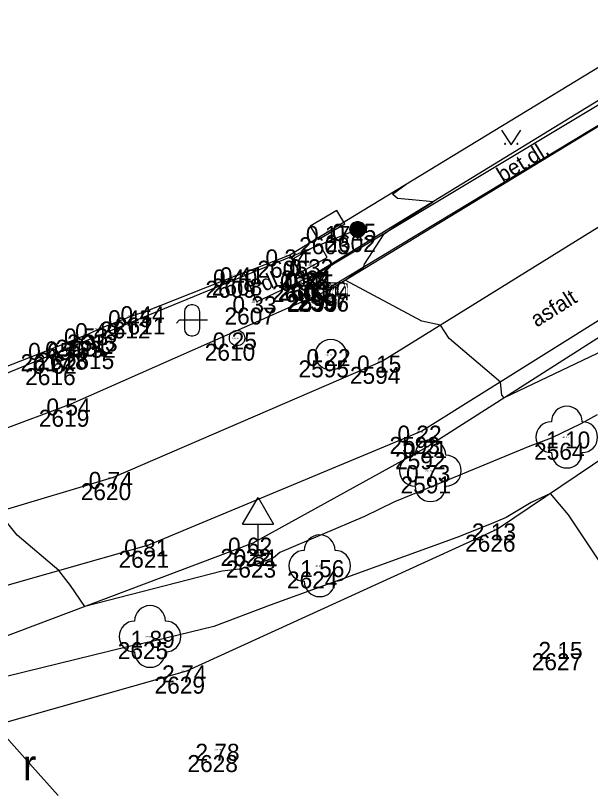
# Model space of a CAD drawing. Extents: x -740053 to -737517, y -1033516 to -1032488.
# Drawn here: x -738693.03 to -738674.39, y -1032632.11 to -1032606.84 of the extents above; entities that cross this region are included whole.
import ezdxf

# ---------------------------------------------------------------- set-up
doc = ezdxf.new("R2010")
doc.units = 0
for name, color, linetype in [('bod-cislo', 7, 'Continuous'), ('bod-oznac', 7, 'Continuous'), ('bod-vyska', 7, 'Continuous'), ('bod-vyska100', 7, 'Continuous'), ('Contours', 7, 'Continuous'), ('Contours highlighted', 7, 'Continuous'), ('dopr-zariz', 7, 'Continuous'), ('el-zariz', 7, 'Continuous'), ('nazvy-bud-povr', 7, 'Continuous'), ('objekty-na-kanalizaci', 7, 'Continuous'), ('objekty-na-vodovodu', 7, 'Continuous'), ('obrubnik', 7, 'Continuous'), ('osa-komunikace', 7, 'Continuous'), ('Ploty-Vjezd', 7, 'Continuous'), ('podezdivka', 7, 'Continuous'), ('Rozhrani-ploch', 7, 'Continuous'), ('Sdelovaci', 7, 'Continuous'), ('silnice', 7, 'Continuous'), ('Terenni-hrana', 7, 'Continuous'), ('Znacky-kultury', 7, 'Continuous')]:
    doc.layers.add(name, color=color, linetype=linetype)

# ---------------------------------------------------------------- blocks, each defined once
blk = doc.blocks.new('POINT_DISPLAY')
blk.add_line((0, 0), (0, 0))
blk = doc.blocks.new('p_strom')
for centre, start, end in [((0, 1), 0, 180), ((-1, 0), 90, 270), ((1, 0), 270, 90), ((0, -1), 180, 0)]:
    blk.add_arc(centre, 1, start, end)
at = {"rotation": -180}
blk.add_blockref('POINT_DISPLAY', (0, 0), dxfattribs=at)
blk = doc.blocks.new('po_kansa')
blk.add_circle((0, 0), 1)
blk = doc.blocks.new('_U')
for points in [[(-4999.05, -6988.837), (-4999.045, -6988.908), (-4999.045, -6988.765), (-4999.045, -6988.765)], [(-4999.045, -6988.765), (-4999.03, -6988.977), (-4999.03, -6988.696), (-4999.03, -6988.696)], [(-4999.03, -6988.977), (-4999.045, -6988.765), (-4999.045, -6988.908), (-4999.045, -6988.908)], [(-4999.03, -6988.696), (-4999.005, -6989.044), (-4999.005, -6988.629), (-4999.005, -6988.629)], [(-4999.005, -6989.044), (-4999.03, -6988.696), (-4999.03, -6988.977), (-4999.03, -6988.977)], [(-4999.005, -6988.629), (-4998.971, -6989.107), (-4998.971, -6988.566), (-4998.971, -6988.566)], [(-4998.971, -6989.107), (-4999.005, -6988.629), (-4999.005, -6989.044), (-4999.005, -6989.044)], [(-4998.971, -6988.566), (-4998.928, -6989.164), (-4998.928, -6988.509), (-4998.928, -6988.509)], [(-4998.928, -6989.164), (-4998.971, -6988.566), (-4998.971, -6989.107), (-4998.971, -6989.107)], [(-4998.928, -6988.509), (-4998.878, -6989.214), (-4998.878, -6988.459), (-4998.878, -6988.459)], [(-4998.878, -6989.214), (-4998.928, -6988.509), (-4998.928, -6989.164), (-4998.928, -6989.164)], [(-4998.878, -6988.459), (-4998.82, -6989.257), (-4998.82, -6988.416), (-4998.82, -6988.416)], [(-4998.82, -6989.257), (-4998.878, -6988.459), (-4998.878, -6989.214), (-4998.878, -6989.214)], [(-4998.82, -6988.416), (-4998.758, -6989.291), (-4998.758, -6988.382), (-4998.758, -6988.382)], [(-4998.758, -6989.291), (-4998.82, -6988.416), (-4998.82, -6989.257), (-4998.82, -6989.257)], [(-4998.758, -6988.382), (-4998.691, -6989.316), (-4998.691, -6988.357), (-4998.691, -6988.357)], [(-4998.691, -6989.316), (-4998.758, -6988.382), (-4998.758, -6989.291), (-4998.758, -6989.291)], [(-4998.691, -6988.357), (-4998.621, -6989.331), (-4998.621, -6988.342), (-4998.621, -6988.342)], [(-4998.621, -6989.331), (-4998.691, -6988.357), (-4998.691, -6989.316), (-4998.691, -6989.316)], [(-4998.621, -6988.342), (-4998.55, -6989.336), (-4998.55, -6988.337), (-4998.55, -6988.337)], [(-4998.55, -6989.336), (-4998.621, -6988.342), (-4998.621, -6989.331), (-4998.621, -6989.331)], [(-4998.55, -6988.337), (-4998.479, -6989.331), (-4998.479, -6988.342), (-4998.479, -6988.342)], [(-4998.479, -6989.331), (-4998.55, -6988.337), (-4998.55, -6989.336), (-4998.55, -6989.336)], [(-4998.479, -6988.342), (-4998.409, -6989.316), (-4998.409, -6988.357), (-4998.409, -6988.357)], [(-4998.409, -6989.316), (-4998.479, -6988.342), (-4998.479, -6989.331), (-4998.479, -6989.331)], [(-4998.409, -6988.357), (-4998.343, -6989.291), (-4998.343, -6988.382), (-4998.343, -6988.382)], [(-4998.343, -6989.291), (-4998.409, -6988.357), (-4998.409, -6989.316), (-4998.409, -6989.316)], [(-4998.343, -6988.382), (-4998.28, -6989.257), (-4998.28, -6988.416), (-4998.28, -6988.416)], [(-4998.28, -6989.257), (-4998.343, -6988.382), (-4998.343, -6989.291), (-4998.343, -6989.291)], [(-4998.28, -6988.416), (-4998.223, -6989.214), (-4998.223, -6988.459), (-4998.223, -6988.459)], [(-4998.223, -6989.214), (-4998.28, -6988.416), (-4998.28, -6989.257), (-4998.28, -6989.257)], [(-4998.223, -6988.459), (-4998.173, -6989.164), (-4998.173, -6988.509), (-4998.173, -6988.509)], [(-4998.173, -6989.164), (-4998.223, -6988.459), (-4998.223, -6989.214), (-4998.223, -6989.214)], [(-4998.173, -6988.509), (-4998.13, -6989.107), (-4998.13, -6988.566), (-4998.13, -6988.566)], [(-4998.13, -6989.107), (-4998.173, -6988.509), (-4998.173, -6989.164), (-4998.173, -6989.164)], [(-4998.13, -6988.566), (-4998.096, -6989.044), (-4998.096, -6988.629), (-4998.096, -6988.629)], [(-4998.096, -6989.044), (-4998.13, -6988.566), (-4998.13, -6989.107), (-4998.13, -6989.107)], [(-4998.096, -6988.629), (-4998.071, -6988.977), (-4998.071, -6988.696), (-4998.071, -6988.696)], [(-4998.071, -6988.977), (-4998.096, -6988.629), (-4998.096, -6989.044), (-4998.096, -6989.044)], [(-4998.071, -6988.696), (-4998.056, -6988.908), (-4998.056, -6988.765), (-4998.056, -6988.765)], [(-4998.056, -6988.908), (-4998.071, -6988.696), (-4998.071, -6988.977), (-4998.071, -6988.977)], [(-4998.05, -6988.837), (-4998.056, -6988.765), (-4998.056, -6988.908), (-4998.056, -6988.908)]]:
    blk.add_lwpolyline(points, close=True)
blk = doc.blocks.new('el_sloup')
blk.add_circle((0, 0), 0.5)
blk.add_blockref('_U', (4998.55, 6988.837))
blk = doc.blocks.new('el_rozd')
for p, q in [((-1.001, 1.001), (-1.001, 0)), ((1.001, 1.001), (-1.001, 1.001)), ((1.001, 0), (1.001, 1.001)), ((-1.001, 0), (1.001, 0))]:
    blk.add_line(p, q)
blk = doc.blocks.new('vo_soupe')
blk.add_circle((0, 0), 0.5)
blk = doc.blocks.new('d_znacka')
for p, q in [((-1, 2), (0, 3.732)), ((0, 3.732), (1, 2)), ((-1, 2), (1, 2)), ((0, 0), (0, 2)), ((-0.5, 0), (0.5, 0))]:
    blk.add_line(p, q)
blk = doc.blocks.new('p_park')
for p, q in [((-1.002, 1.5), (0, 0)), ((0, 0), (1.002, 1.5))]:
    blk.add_line(p, q)
for centre, start, end in [((-0.623, 0.102), 360, 180), ((-0.623, 0.102), 180, 360), ((0.658, 0.102), 0, 180), ((0.658, 0.102), 180, 0)]:
    blk.add_arc(centre, 0.05, start, end)
blk = doc.blocks.new('p_neplod')
for p, q in [((-0.494, 0.555), (-0.494, -0.548)), ((0.052, 1.005), (-0.044, 1.005)), ((0.502, -0.548), (0.502, 0.555)), ((-0.824, 0.004), (-0.994, -0.184)), ((1.002, 0.004), (-0.824, 0.004)), ((-0.044, -0.998), (0.052, -0.998))]:
    blk.add_line(p, q)
for centre, start, end in [((-0.044, 0.555), 90, 180), ((0.052, 0.555), 0, 90), ((-0.044, -0.548), 180, 270), ((0.052, -0.548), 270, 0)]:
    blk.add_arc(centre, 0.45, start, end)
blk = doc.blocks.new('p_orna')
blk.add_text('r', height=1.996).set_placement((-0.002, 0))

msp = doc.modelspace()

# ---------------------------------------------------------------- linework, layer by layer
at = {"layer": 'Contours'}
for points in [[(-738674.176, -1032619.78), (-738674.7, -1032620.069), (-738675.668, -1032620.535), (-738676.355, -1032620.795), (-738679.161, -1032621.954), (-738680.748, -1032622.592), (-738681.722, -1032623.069), (-738684.463, -1032624.235), (-738684.663, -1032624.409), (-738685.398, -1032624.69), (-738685.786, -1032624.784), (-738686.336, -1032624.844), (-738690.782, -1032625.989), (-738691.248, -1032625.307), (-738691.624, -1032624.827), (-738692.982, -1032623.673), (-738693.598, -1032622.921), (-738695.368, -1032622.283), (-738696.983, -1032621.582), (-738695.728, -1032620.214), (-738695.568, -1032619.535), (-738695.572, -1032619.332), (-738695.495, -1032619.066)], [(-738673.049, -1032626.1), (-738675.104, -1032623.02), (-738675.691, -1032622.326), (-738676.313, -1032622.616), (-738677.126, -1032623.104), (-738677.611, -1032623.305), (-738678.724, -1032623.751), (-738684.781, -1032625.942), (-738686.6, -1032626.638), (-738688.517, -1032627.105), (-738689.404, -1032627.297), (-738697.254, -1032629.216), (-738699.629, -1032629.462), (-738706.445, -1032630.229), (-738706.608, -1032630.027), (-738706.158, -1032628.364), (-738706.481, -1032626.699), (-738706.759, -1032626.307), (-738707.157, -1032626.093), (-738709.238, -1032624.356), (-738709.051, -1032623.478), (-738709.105, -1032623.213), (-738709.776, -1032623.115), (-738711.586, -1032622.343)], [(-738691.646, -1032632.111), (-738692.477, -1032631.182), (-738693.678, -1032629.842), (-738696.076, -1032630.361), (-738697.04, -1032630.597), (-738703.814, -1032631.3), (-738707.302, -1032631.693), (-738712.466, -1032631.794), (-738712.64, -1032631.79)]]:
    msp.add_lwpolyline(points, dxfattribs=at)
at = {"layer": 'Contours highlighted'}
msp.add_lwpolyline([(-738670.249, -1032615.922), (-738677.188, -1032619.224), (-738677.266, -1032619.14), (-738677.314, -1032618.716), (-738678.978, -1032617.306), (-738679.251, -1032616.874), (-738679.855, -1032616.74), (-738682.347, -1032615.419), (-738682.342, -1032615.414), (-738681.753, -1032614.998), (-738681.721, -1032614.9), (-738681.079, -1032613.907), (-738680.604, -1032613.578), (-738679.494, -1032612.874), (-738680.175, -1032612.812), (-738680.65, -1032612.768), (-738680.811, -1032612.626), (-738680.367, -1032612.306)], dxfattribs=at)
at = {"layer": 'obrubnik'}
for p, q in [((-738673.35, -1032609.11), (-738683.52, -1032615.34)), ((-738672.98, -1032609.7), (-738682.85, -1032615.66)), ((-738683.652, -1032615.372), (-738684.14, -1032614.6)), ((-738683.67, -1032615.39), (-738683.652, -1032615.372)), ((-738683.52, -1032615.34), (-738683.652, -1032615.372)), ((-738683.19, -1032615.67), (-738683.48, -1032615.35)), ((-738683.023, -1032615.692), (-738683.19, -1032615.67)), ((-738682.85, -1032615.66), (-738683.023, -1032615.692))]:
    msp.add_line(p, q, dxfattribs=at)
at = {"layer": 'osa-komunikace'}
for p, q in [((-738671.61, -1032612.13), (-738681.13, -1032618.04)), ((-738681.13, -1032618.04), (-738689.87, -1032621.81)), ((-738689.87, -1032621.81), (-738698.33, -1032624.33))]:
    msp.add_line(p, q, dxfattribs=at)
at = {"layer": 'Ploty-Vjezd'}
for p, q in [((-738685.84, -1032615.25), (-738688.84, -1032616.44)), ((-738689.24, -1032616.57), (-738690.31, -1032616.99)), ((-738690.673, -1032617.162), (-738691.817, -1032617.629))]:
    msp.add_line(p, q, dxfattribs=at)
at = {"layer": 'podezdivka'}
for p, q in [((-738671.38, -1032606.84), (-738684.14, -1032614.6)), ((-738684.14, -1032614.6), (-738685.62, -1032615.18)), ((-738685.62, -1032615.18), (-738685.84, -1032615.25)), ((-738688.84, -1032616.44), (-738689.24, -1032616.57)), ((-738690.31, -1032616.99), (-738690.67, -1032617.16)), ((-738691.82, -1032617.63), (-738698.96, -1032620.42))]:
    msp.add_line(p, q, dxfattribs=at)
at = {"layer": 'Rozhrani-ploch'}
for p, q in [((-738673.25, -1032609.2), (-738683.48, -1032615.35)), ((-738683.67, -1032615.39), (-738684.14, -1032614.6)), ((-738685.21, -1032616.12), (-738685.62, -1032615.18)), ((-738683.67, -1032615.39), (-738685.21, -1032616.12)), ((-738683.48, -1032615.35), (-738683.67, -1032615.39)), ((-738683.19, -1032615.71), (-738683.48, -1032615.35)), ((-738683.019, -1032615.73), (-738683.19, -1032615.71)), ((-738682.81, -1032615.7), (-738683.019, -1032615.73)), ((-738690.434, -1032617.556), (-738690.673, -1032617.162)), ((-738690.67, -1032617.16), (-738690.42, -1032617.56)), ((-738690.42, -1032617.56), (-738691.67, -1032618.08)), ((-738691.666, -1032618.073), (-738690.434, -1032617.556)), ((-738691.67, -1032618.08), (-738691.82, -1032617.63)), ((-738691.817, -1032617.629), (-738691.666, -1032618.073))]:
    msp.add_line(p, q, dxfattribs=at)
at = {"layer": 'Sdelovaci'}
msp.add_line((-738681.94, -1032613.77), (-738700.2, -1032621.25), dxfattribs=at)
at = {"layer": 'silnice'}
for p, q in [((-738672.97, -1032609.72), (-738682.81, -1032615.7)), ((-738670.37, -1032614.37), (-738679.86, -1032620.31)), ((-738682.81, -1032615.7), (-738691.24, -1032619.43)), ((-738691.24, -1032619.43), (-738698.98, -1032622.33)), ((-738679.86, -1032620.31), (-738688.72, -1032624)), ((-738688.72, -1032624), (-738697.89, -1032626.61))]:
    msp.add_line(p, q, dxfattribs=at)
at = {"layer": 'Terenni-hrana'}
for p, q in [((-738666.39, -1032612.35), (-738679.68, -1032620.81)), ((-738665.38, -1032615.4), (-738677.41, -1032623.48)), ((-738679.68, -1032620.81), (-738685.34, -1032623.94)), ((-738677.41, -1032623.48), (-738687.49, -1032628.08)), ((-738685.34, -1032623.94), (-738697.37, -1032628.47)), ((-738687.49, -1032628.08), (-738697.01, -1032630.79))]:
    msp.add_line(p, q, dxfattribs=at)

# ---------------------------------------------------------------- block references
at = {"layer": 'bod-oznac'}
for p in [(-738681.94, -1032613.77), (-738682.79, -1032613.84), (-738684.14, -1032614.6), (-738683.37, -1032614.92), (-738685.84, -1032615.25), (-738685.62, -1032615.18), (-738683.67, -1032615.39), (-738683.52, -1032615.34), (-738683.48, -1032615.35), (-738683.19, -1032615.67), (-738683.19, -1032615.71), (-738682.85, -1032615.66), (-738682.81, -1032615.7), (-738685.21, -1032616.12), (-738688.84, -1032616.44), (-738689.24, -1032616.57), (-738690.31, -1032616.99), (-738690.67, -1032617.16), (-738685.85, -1032617.29), (-738690.42, -1032617.56), (-738691.82, -1032617.63), (-738691.28, -1032617.58), (-738691.67, -1032618.08), (-738682.81, -1032617.83), (-738681.13, -1032618.04), (-738691.24, -1032619.43), (-738679.86, -1032620.31), (-738675.16, -1032620.5), (-738679.68, -1032620.81), (-738679.58, -1032621.59), (-738689.87, -1032621.81), (-738677.41, -1032623.48), (-738688.72, -1032624), (-738685.34, -1032623.94), (-738685.17, -1032624.32), (-738683.17, -1032624.67), (-738688.67, -1032626.96), (-738675.25, -1032627.32), (-738687.49, -1032628.08), (-738686.41, -1032630.62)]:
    msp.add_blockref('POINT_DISPLAY', p, dxfattribs=at)
at = {"layer": 'dopr-zariz', "xscale": 0.5, "yscale": 0.5}
msp.add_blockref('d_znacka', (-738685.17, -1032624.32), dxfattribs=at)
at = {"layer": 'el-zariz'}
for p, xscale, yscale, rotation in [((-738682.79, -1032613.84), 0.49999999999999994, 0.4999999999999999, 30.52115502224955), ((-738683.37, -1032614.92), 0.5, 0.5, 29.33989546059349)]:
    msp.add_blockref('el_rozd', p, dxfattribs=dict(at, xscale=xscale, yscale=yscale, rotation=rotation))
at = {"layer": 'el-zariz', "xscale": 0.5, "yscale": 0.5}
msp.add_blockref('el_sloup', (-738681.94, -1032613.77), dxfattribs=at)
at = {"layer": 'objekty-na-kanalizaci', "xscale": 0.5, "yscale": 0.5}
msp.add_blockref('po_kansa', (-738682.81, -1032617.83), dxfattribs=at)
at = {"layer": 'objekty-na-vodovodu', "xscale": 0.5, "yscale": 0.5}
msp.add_blockref('vo_soupe', (-738685.85, -1032617.29), dxfattribs=at)
at = {"layer": 'Znacky-kultury'}
for name, p, xscale, yscale in [('p_park', (-738676.966, -1032611.03), 0.31490742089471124, 0.31490742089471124), ('p_neplod', (-738687.311, -1032616.715), 0.5, 0.5), ('p_strom', (-738675.16, -1032620.5), 0.5, 0.5), ('p_strom', (-738679.58, -1032621.59), 0.5, 0.5), ('p_strom', (-738683.17, -1032624.67), 0.5, 0.5), ('p_strom', (-738688.67, -1032626.96), 0.5, 0.5), ('p_orna', (-738692.799, -1032631.62), 0.5, 0.5)]:
    msp.add_blockref(name, p, dxfattribs=dict(at, xscale=xscale, yscale=yscale))

# ---------------------------------------------------------------- texts
at = {"layer": 'bod-cislo'}
for s, p in [('2603', (-738683.838, -1032614.573)), ('2602', (-738682.988, -1032614.503)), ('2606', (-738685.188, -1032615.333)), ('2604', (-738684.431, -1032615.653)), ('2609', (-738686.875, -1032615.983)), ('2608', (-738686.668, -1032615.913)), ('2600', (-738684.528, -1032616.083)), ('2601', (-738684.489, -1032616.073)), ('2605', (-738684.718, -1032616.123)), ('2598', (-738684.238, -1032616.403)), ('2599', (-738684.225, -1032616.443)), ('2597', (-738683.898, -1032616.393)), ('2596', (-738683.858, -1032616.433)), ('2607', (-738686.258, -1032616.853)), ('2612', (-738690.288, -1032617.303)), ('2611', (-738689.809, -1032617.173)), ('2613', (-738691.358, -1032617.723)), ('2614', (-738691.731, -1032617.893)), ('2610', (-738686.898, -1032618.023)), ('2617', (-738692.868, -1032618.363)), ('2618', (-738692.328, -1032618.313)), ('2615', (-738691.468, -1032618.293)), ('2595', (-738683.858, -1032618.563)), ('2616', (-738692.718, -1032618.813)), ('2594', (-738682.191, -1032618.773)), ('2619', (-738692.275, -1032620.163)), ('2593', (-738680.908, -1032621.043)), ('2564', (-738676.221, -1032621.233)), ('2592', (-738680.728, -1032621.543)), ('2591', (-738680.549, -1032622.323)), ('2620', (-738690.918, -1032622.543)), ('2626', (-738678.458, -1032624.213)), ('2622', (-738686.388, -1032624.673)), ('2621', (-738689.689, -1032624.733)), ('2623', (-738686.218, -1032625.053)), ('2624', (-738684.231, -1032625.403)), ('2625', (-738689.718, -1032627.693)), ('2627', (-738676.298, -1032628.053)), ('2629', (-738688.525, -1032628.813)), ('2628', (-738687.458, -1032631.353))]:
    msp.add_text(s, height=0.55, dxfattribs=at).set_placement(p)
at = {"layer": 'bod-vyska'}
for s, p in [('0 17', (-738683.618, -1032614.207)), ('0 15', (-738682.768, -1032614.137)), ('0 34', (-738684.929, -1032614.967)), ('0 32', (-738684.159, -1032615.287)), ('0 41', (-738686.409, -1032615.547)), ('0 40', (-738686.629, -1032615.617)), ('0 37', (-738684.459, -1032615.757)), ('0 38', (-738684.309, -1032615.707)), ('0 23', (-738684.269, -1032615.717)), ('0 17', (-738684.018, -1032616.037)), ('0 11', (-738684.018, -1032616.077)), ('0 10', (-738683.678, -1032616.027)), ('0 04', (-738683.599, -1032616.067)), ('0 33', (-738685.999, -1032616.487)), ('0 44', (-738689.629, -1032616.807)), ('0 45', (-738690.029, -1032616.937)), ('0 49', (-738691.099, -1032617.357)), ('0 53', (-738691.459, -1032617.527)), ('0 25', (-738686.639, -1032617.657)), ('0 65', (-738692.622, -1032617.997)), ('0 76', (-738692.069, -1032617.947)), ('0 52', (-738691.209, -1032617.927)), ('0 22', (-738683.599, -1032618.197)), ('0 62', (-738692.472, -1032618.447)), ('0 15', (-738681.958, -1032618.407)), ('0 54', (-738692.029, -1032619.797)), ('0 22', (-738680.649, -1032620.677)), ('1 10', (-738675.831, -1032620.867)), ('0 21', (-738680.469, -1032621.177)), ('0 73', (-738680.369, -1032621.957)), ('0 74', (-738690.659, -1032622.177)), ('2 13', (-738678.238, -1032623.847)), ('0 81', (-738689.509, -1032624.367)), ('0 62', (-738686.142, -1032624.307)), ('0 81', (-738685.959, -1032624.687)), ('1 56', (-738683.802, -1032625.037)), ('1 89', (-738689.302, -1032627.327)), ('2 15', (-738676.078, -1032627.687)), ('2 74', (-738688.279, -1032628.447)), ('2 78', (-738687.199, -1032630.987))]:
    msp.add_text(s, height=0.55, dxfattribs=at).set_placement(p)
at = {"layer": 'bod-vyska100'}
for s, p in [('280 15', (-738682.111, -1032613.803)), ('280 17', (-738682.961, -1032613.873)), ('280 34', (-738684.307, -1032614.633)), ('280 32', (-738683.537, -1032614.953)), ('280 40', (-738686.007, -1032615.283)), ('280 41', (-738685.787, -1032615.213)), ('280 37', (-738683.837, -1032615.423)), ('280 38', (-738683.687, -1032615.373)), ('280 23', (-738683.647, -1032615.383)), ('280 17', (-738683.361, -1032615.703)), ('280 11', (-738683.361, -1032615.743)), ('280 10', (-738683.021, -1032615.693)), ('280 04', (-738682.977, -1032615.733)), ('280 33', (-738685.377, -1032616.153)), ('280 45', (-738689.407, -1032616.603)), ('280 44', (-738689.007, -1032616.473)), ('280 49', (-738690.477, -1032617.023)), ('280 53', (-738690.837, -1032617.193)), ('280 25', (-738686.017, -1032617.323)), ('280 76', (-738691.447, -1032617.613)), ('280 52', (-738690.587, -1032617.593)), ('280 65', (-738691.988, -1032617.663)), ('280 22', (-738682.977, -1032617.863)), ('280 62', (-738691.838, -1032618.113)), ('280 15', (-738681.301, -1032618.073)), ('280 54', (-738691.407, -1032619.463)), ('280 22', (-738680.027, -1032620.343)), ('281 10', (-738675.323, -1032620.533)), ('280 21', (-738679.847, -1032620.843)), ('280 73', (-738679.747, -1032621.623)), ('280 74', (-738690.037, -1032621.843)), ('282 13', (-738677.581, -1032623.513)), ('280 81', (-738688.887, -1032624.033)), ('280 62', (-738685.508, -1032623.973)), ('280 81', (-738685.337, -1032624.353)), ('281 56', (-738683.33, -1032624.703)), ('281 89', (-738688.83, -1032626.993)), ('282 15', (-738675.421, -1032627.353)), ('282 74', (-738687.657, -1032628.113)), ('282 78', (-738686.577, -1032630.653))]:
    msp.add_text(s, height=0.05, dxfattribs=at).set_placement(p)
at = {"layer": 'nazvy-bud-povr'}
for s, height, rotation, p in [('bet.dl.', 0.5, 31.5547, (-738677.236, -1032612.26)), ('dl.', 0.5, 24.2283, (-738684.956, -1032615.789)), ('asfalt', 0.5, 32.1173, (-738676.136, -1032616.954)), ('bet.', 0.2586, 22.1727, (-738691.368, -1032617.852))]:
    msp.add_text(s, height=height, rotation=rotation, dxfattribs=at).set_placement(p)

doc.saveas('drawing.dxf')
